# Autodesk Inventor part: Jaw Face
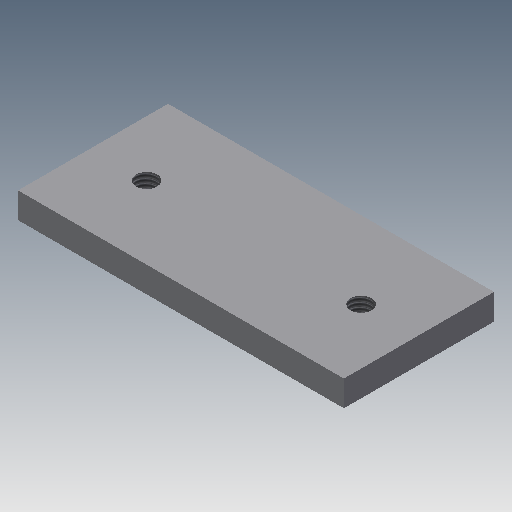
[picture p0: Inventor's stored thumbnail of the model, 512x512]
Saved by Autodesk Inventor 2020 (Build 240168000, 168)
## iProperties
Created: 2002-02
Part Number: Jaw Face
Document SubType Name: Modeling
Designer: ***
Density: 1 g/cm^3
Material: Generic
Mass: 15.6207 g
Surface Area: 67.651 cm^2
Volume: 15.6207 cm^3
Appearance: Default
Control State: 0
Master: False
Checked Out: False
Shininess: 77.0
Length Units: 11269
Angle Units: 11279
Time Units: 11290
Mass Units: 11283
Length Display Precision: 3
Angle Display Precision: 2
Compacted: True
Density: 0.0
Volumn: 0.0
Area: 0.0
PropertySet Name: Model Information
Author: ***
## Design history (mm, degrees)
sketch "Sketch1"
  geometry: L1 (-79.661, -8.43)-(-3.661, -8.43); L2 (-3.661, -8.43)-(-3.661, -43.43); L3 (-3.661, -43.43)-(-79.661, -43.43); L4 (-79.661, -43.43)-(-79.661, -8.43)
  constraints: 8 end point, 2 parallel, 1 horizontal, 1 perpendicular
  dimensions: "d0" = 76 distance of L2.end L3.end; "d3" = 35 distance of L1.end L2.end
extrude "Extrusion1" new body sketch "Sketch1" stored distance "d7" = 6; taper "d8" = 0 deg
hole "Hole1" diameter "d11" = 4.917; stored, may be unused: countersink angle "d15" = 90 deg, drill point angle "d17" = 118 deg; dims "d9" = 13, "d10" = 18, "d12" = 12, "d13" = 4, "d14" = 2, "d16" = 17.1
pattern_linear "Rectangular Pattern1" dims "d20" = -50
body "Solid1"
